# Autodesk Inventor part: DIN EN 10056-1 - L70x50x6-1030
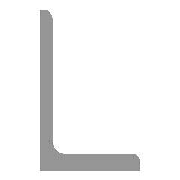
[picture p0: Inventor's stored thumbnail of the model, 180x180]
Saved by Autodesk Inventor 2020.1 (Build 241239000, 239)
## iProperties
Created: 2019-01
Part Number: DIN EN 10056-1 - L70x50x6-1030
Material: Stahl, weich
Description: Warmgewalztes Baustahlprofil - ungleichschenklig
Document SubType Name: Modeling
Standard: DIN
Designer: lutzd
Standard Revision: 1998
Standards Organization: DIN
Language: de-DE
Size Designation: L70x50x6
Categories: <MemberInstance><Categories><Category DisplayName="Profile" InternalName="089c4875-fa83-4c05-b084-43b9cc11f5ed" Mnemonic="GRDR"><CategoryParameter DisplayName="
Stock Number: L70x50x6
Mass: 5438.61 g
Surface Area: 2377.97 cm^2
Volume: 692.817 cm^3
Density: 7.85 g/cm^3
Appearance: Semi-Polished(8)
IsCustomPart: 1
G_L: 1030,000 mm
G_W: 50,000 mm
G_H: 70,000 mm
DocNumber: ADSK-014335
Folder: .
Dimensions: 70x1030x50 mm
Mass: 5,439 kg
VLT_Material: Stahl, weich
_CCFamilyMember: 110
_CCFamilyDisplayName: DIN EN 10056-1 (L-Profil) - Warmgewalztes Baustahlprofil - ungleichschenklig
_FrameMemberDoc: Frame Member File
_Version: 15.0.0
_GetPNFromCC: 1
Title: Profil-Bauteil
Author: lutzd
Revision Number: -
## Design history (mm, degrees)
node "Startebene"
node "Endebene"
sketch "Skizze"
  geometry: L1 (-6.5, 44.2)-(-6.5, -9.3); L2 (-12.5, 47.7)-(-10, 47.7); L3 (-12.5, -22.3)-(-12.5, 47.7); L4 (37.5, -22.3)-(-12.5, -22.3); L5 (37.5, -19.8)-(37.5, -22.3); L6 (0.5, -16.3)-(34, -16.3); L7 (0, 62.57)-(0, -36.445) reference; L8 (-22.645, 0)-(48.37, 0) reference; A1 r 7 centre (0.5, -9.3) between (-6.5, -9.3) and (0.5, -16.3); A2 r 3.5 centre (-10, 44.2) between (-6.5, 44.2) and (-10, 47.7); A3 r 3.5 centre (34, -19.8) between (37.5, -19.8) and (34, -16.3); 3 further points
  constraints: 12 end point, 6 point on circle, 6 point on line, 6 tangent, 3 centre point, 3 horizontal, 3 vertical, 1 equal radius
  dimensions: "d4" = 50 distance of L4.start L3.start (= b); "d6" = 70 distance of L3.start L2.start (= ParH); "d8" = 6 distance of point (37.5, -16.3) L4.start (= ParT); "d10" = 6 distance of L2.start point (-6.5, 47.7) (= ParT); "d17" = 7 radius of A1 (= R); "d18" = 3.5 radius of A2 (= R1); "d19" = 22.3 distance between parallel lines of L8 L4 (= ex); "d20" = 12.5 distance between parallel lines of L3 L7 (= ey)
extrude "Körper" new body sketch "Skizze" stored distance "d11" = 1030 (= G_L); taper "d12" = 0 deg
node "Driven Length"
  sketch "Sketch3"
    geometry: L1 (0, 0)-(10, 0) reference
    constraints: 2 end point, 1 horizontal
  workplane "Work Plane10"
  sketch "Sketch4"
    geometry: L1 (-2, 0)-(12, 0) reference; L2 (-2, 1030)-(12, 1030) reference
    dimensions: "d24" = 1030 distance between parallel lines of L1 L2 (derived)
sketch "Skizze5"
  geometry: L1 (50, 0)-(50, 1030) reference; L2 (50, 0)-(0, 0) reference; L3 (12, 0)-(50, 50); L4 (50, 1030)-(0, 1030) reference; L5 (12, 1030)-(50, 980); 1 further point
  constraints: 4 end point, 4 point on line, 1 vertical alignment
  dimensions: "d25" = 50 vertical distance of L3.start L3.end; "d26" = 38 horizontal distance of L3.start L3.end; "d27" = 50 vertical distance of L5.start L5.end (= d25)
extrude "Extrusion2" cut sketch "Skizze5" distance "d28" = 10; taper "d29" = 0 deg
sketch "Skizze6"
  geometry: L1 (445, 22)-(485, 22); L2 (445, 15.5)-(485, 15.5); L3 (485, 28.5)-(445, 28.5); L4 (0, 53.5)-(0, 0) reference; L5 (19, 22)-(31, 22); L6 (19, 17.5)-(31, 17.5); L7 (31, 26.5)-(19, 26.5); L8 (1030, 57)-(0, 57) reference; L9 (999, 22)-(1011, 22); L10 (999, 17.5)-(1011, 17.5); L11 (1011, 26.5)-(999, 26.5); L12 (1030, 53.5)-(1030, 0) reference; A1 r 6.5 centre (445, 22) between (445, 28.5) and (445, 15.5); A2 r 6.5 centre (485, 22) between (485, 15.5) and (485, 28.5); A3 r 4.5 centre (19, 22) between (19, 26.5) and (19, 17.5); A4 r 4.5 centre (31, 22) between (31, 17.5) and (31, 26.5); A5 r 4.5 centre (1011, 22) between (1011, 17.5) and (1011, 26.5); A6 r 4.5 centre (999, 22) between (999, 26.5) and (999, 17.5); 4 further points
  constraints: 24 end point, 12 point on circle, 12 tangent, 6 centre point, 3 horizontal, 3 midpoint, 3 parallel, 2 collinear
  dimensions: "d30" = 445 distance from line of L4 L1.start; "d31" = 40 distance of L3.start L3.end; "d32" = 13 distance between parallel lines of L2 L3; "d33" = 25 distance from line of point (25, 22) L4; "d34" = 35 distance between parallel lines of L8 L5; "d35" = 9 distance between parallel lines of L6 L7; "d36" = 12 distance of L5.start L5.end; "d37" = 9 distance between parallel lines of L10 L11; "d38" = 12 distance of L9.start L9.end; "d39" = 25 distance from line of L12 point (1005, 22)
extrude "Extrusion3" cut sketch "Skizze6" extent not by distance; stored distance "d40" = 44; taper "d41" = 0 deg
workplane "Arbeitsebene11"
body "Solid1"
other parameters: "b" = 50 [user parameter; used in 1 equation term], "ParT" = 6 [user parameter; used in 2 equation terms], "R1" = 3.5 [user parameter; used in 1 equation term], "G_L" = 1030 (= d24) [user parameter; used in 1 equation term], "ParH" = 70 [user parameter; used in 1 equation term], "R" = 7 [user parameter; used in 1 equation term], "d7" = 4 (derived), "d9" = 4 (derived), "ey" = 12.5 [user parameter; used in 1 equation term], "ex" = 22.3 [user parameter; used in 1 equation term], "G_OFFSET_START" = 0 [user parameter; used in 1 equation term], "G_OFFSET_END" = 0 [user parameter; used in 1 equation term], "d21" = 0 (computed from G_OFFSET_START), "d23" = 90 deg
